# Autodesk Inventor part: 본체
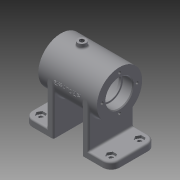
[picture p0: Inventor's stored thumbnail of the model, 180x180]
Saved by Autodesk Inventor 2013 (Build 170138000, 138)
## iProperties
Created: 2017-02
Part Number: 본체
Material: 일반
Document SubType Name: Modeling
Designer: Administrator
Density: 1 g/cm^3
Author: Administrator
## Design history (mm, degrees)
sketch "스케치2"
  geometry: C1 r 27 at (0, 0); 1 further point
  constraints: 1 centre point, 1 coincident
  dimensions: "d0" = 54 diameter of C1
extrude "돌출1" new body sketch "스케치2" stored distance "d1" = 70; taper "d2" = 0 deg
hole "구멍1" diameter "d5" = 28; stored, may be unused: countersink angle "d9" = 90 deg, drill point angle "d11" = 118 deg; dims "d3" = 10, "d4" = 10, "d6" = 6, "d7" = 32, "d8" = 12, "d10" = 8
hole "구멍2" diameter "d14" = 28; stored, may be unused: countersink angle "d18" = 90 deg, drill point angle "d20" = 118 deg; dims "d12" = 10, "d13" = 10, "d15" = 6, "d16" = 32, "d17" = 12, "d19" = 8
sketch "스케치3"
  geometry: C1 r 22 at (0, 0); 1 further point
  constraints: 1 centre point, 1 coincident
  dimensions: "d21" = 44 diameter of C1
extrude "돌출2" cut sketch "스케치3" stored distance "d22" = 40; taper "d23" = 0 deg
sketch "스케치4" dims "d24" = 42
  geometry: C1 r 27 at (0, 0) reference; 3 further points
  constraints: 2 vertical alignment, 1 coincident, 2 other
hole "구멍3" sketch "스케치4" at (0, 21) diameter "d25" = 3.242; stored, may be unused: countersink angle "d29" = 90 deg, drill point angle "d31" = 118 deg; dims "d26" = 8, "d27" = 32, "d28" = 12, "d30" = 10
fillet "모깎기1" dims "d35" = 0.3
fillet "모깎기2" dims "d36" = 3
node "작업 평면1"
sketch "스케치6"
  geometry: L1 (-52, 27)-(-17, 27); L2 (-17, -27)-(-52, -27); L3 (-52, -27)-(-52, 27); L4 (-17, -27)-(-17, -22.125); L5 (-17, -22.125)-(-17, 27); L6 (-52, 0)-(0, 0)
  constraints: 12 end point, 3 perpendicular, 1 horizontal, 1 midpoint, 1 parallel
  dimensions: "d41" = 17 distance from line of L5 L6.end; "d42" = 54 distance of L2.end L1.start; "d43" = 35 distance of L1.start L1.end; "d44" = 52 distance from line of L6.end L3
extrude "돌출3" join sketch "스케치6" distance "d45" = 8; taper "d46" = 0 deg
sketch "스케치7"
  geometry: L1 (-17, 27)-(-17, -27) reference; L2 (-17, 27)-(-25, 27); L3 (-25, 27)-(-25, -27); L4 (-25, -27)-(-17, -27); L5 (-17, -27)-(-17, 27); 1 further point
  constraints: 8 end point, 2 parallel, 1 horizontal, 1 perpendicular
  dimensions: "d47" = 8 distance of L1.start L2.end
extrude "돌출4" join sketch "스케치7" stored distance "d48" = 8; taper "d49" = 0 deg
fillet "모깎기3" dims "d50" = 10
sketch "스케치8"
  geometry: 2 further points
  dimensions: "d51" = 17 vertical distance of point (-42, 17) point (0, 0); "d52" = 42 horizontal distance of point (-42, 17) point (0, 0)
hole "구멍4" sketch "스케치8" at (-42, 17) diameter "d53" = 5; stored, may be unused: countersink angle "d57" = 90 deg, drill point angle "d59" = 118 deg; dims "d54" = 8, "d55" = 32, "d56" = 12, "d58" = 10
sketch "스케치9"
  geometry: L1 (-36.804, 17)-(-39.402, 12.5); L2 (-39.402, 12.5)-(-44.598, 12.5); L3 (-44.598, 12.5)-(-47.196, 17); L4 (-47.196, 17)-(-44.598, 21.5); L5 (-44.598, 21.5)-(-39.402, 21.5); L6 (-39.402, 21.5)-(-36.804, 17); C1 r 2.5 at (-42, 17) reference; C2 r 4.5 at (-42, 17); 2 further points
  constraints: 12 end point, 2 coincident, 1 centre point, 1 horizontal, 13 other
  dimensions: "d60" = 9 distance between parallel lines of L2 L5; "d61" = 9 diameter of C2
extrude "돌출5" cut sketch "스케치9" distance "d62" = 3; taper "d63" = 0 deg
node "작업 평면2"
sketch "스케치10"
  geometry: L1 (-35, 27)-(-35, -27) reference; C1 r 5 at (-10, 0); 1 further point
  constraints: 1 centre point, 1 horizontal alignment
  dimensions: "d108" = 10 diameter of C1; "d109" = 25 distance from line of L1 C1.centre
extrude "돌출6" join sketch "스케치10" stored distance "d66" = 3; taper "d67" = 0 deg
sketch "스케치11"
  geometry: L1 (0, 0)-(0, -27); L2 (0, 0)-(16.339, -25.16); A1 r 27 centre (0, 0) between (-27, 0) and (27, 0) reference; 1 further point
  constraints: 4 end point, 1 coincident, 1 point on circle, 1 vertical
  dimensions: "d77" = 30 distance of L1.start L2.end; "d79" = 33 deg angle of L2 L1
node "작업 평면3"
sketch "스케치12"
  geometry: C1 r 6 at (0, 0); 1 further point
  constraints: 1 centre point, 1 coincident
  dimensions: "d82" = 12 diameter of C1
extrude "돌출7" join sketch "스케치12" stored distance "d83" = 3; taper "d84" = 0 deg
hole "구멍6" diameter "d87" = 5.188; stored, may be unused: countersink angle "d91" = 90 deg, drill point angle "d93" = 118 deg; dims "d85" = 10, "d86" = 10, "d88" = 8, "d89" = 32, "d90" = 12, "d92" = 10
chamfer "모따기1" distance "d94" = 1; stored, may be unused: second distance "d95" = 2, angle "d96" = 45 deg
chamfer "모따기2" distance "d97" = 1; stored, may be unused: second distance "d98" = 2, angle "d99" = 45 deg
fillet "모깎기4" dims "d100" = 2
fillet "모깎기5" dims "d101" = 2
fillet "모깎기6" dims "d102" = 2
node "작업 평면4"
sketch "스케치13"
  geometry: L1 (-29.895, 2.402)-(29.895, 2.402); L2 (29.895, 2.402)-(29.895, -2.402); L3 (29.895, -2.402)-(-29.895, -2.402); L4 (-29.895, -2.402)-(-29.895, 2.402); L5 (-29.895, 0)-(29.895, 0); L6 (0, 2.402)-(0, -2.402); L7 (-35, 27)-(35, 27) reference; L8 (-35, 27)-(-35, -27) reference; 1 further point
  constraints: 4 end point, 4 midpoint, 2 other
  dimensions: "d104" = 27 distance between parallel lines of L7 L5; "d105" = 35 distance between parallel lines of L6 L8
feature "엠보싱1" sketch "스케치13" dims "d0" = 54, "d24" = 42, "d106" = 0.5, "d107" = 0
hole "구멍7" diameter "d112" = 5.188; stored, may be unused: countersink angle "d116" = 90 deg, drill point angle "d118" = 118 deg; dims "d110" = 10, "d111" = 10, "d113" = 8, "d114" = 32, "d115" = 12, "d117" = 10
fillet "모깎기7" dims "d119" = 2
node "솔리드1"
pattern_circular "원형 패턴1" dims angle "d33" = 360 deg
mirror "대칭1"
mirror "대칭2"
mirror "대칭3"
other parameters: "d64" = 92, "d103" = -41.25
